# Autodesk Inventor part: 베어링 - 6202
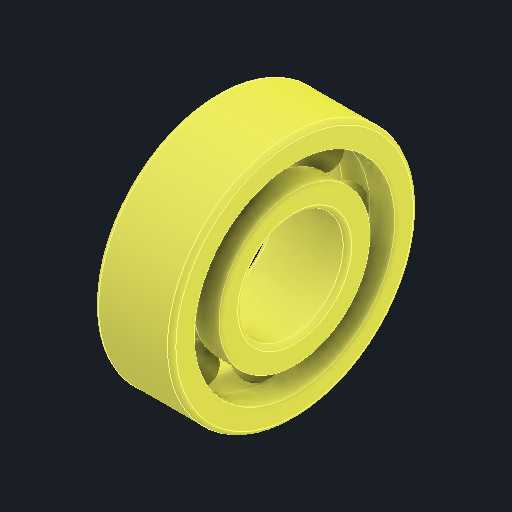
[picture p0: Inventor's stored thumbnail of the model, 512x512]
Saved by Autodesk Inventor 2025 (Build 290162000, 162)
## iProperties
Created: 2025-08
Part Number: 베어링 - 6202
Material: 강, 연강
Description: 깊은 그루브 볼 베어링
Document SubType Name: Modeling
Designer: infra11
Density: 7.86 g/cm^3
Appearance: 기본값
Author: jhkim
Sending System: Autodesk Inventor 2026
Preprocessor: ST-DEVELOPER v20.1
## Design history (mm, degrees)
feature "Solid1"
feature "Solid1:1"
feature "Solid1:2"
feature "Solid1:3"
feature "Solid1:4"
feature "Solid1:5"
feature "Solid1:6"
feature "Solid1:7"
feature "Solid1:8"
feature "Solid1:9"
node "솔리드1"
node "솔리드2"
node "솔리드3"
node "솔리드4"
node "솔리드5"
node "솔리드6"
node "솔리드7"
node "솔리드8"
node "솔리드9"
node "솔리드10"
